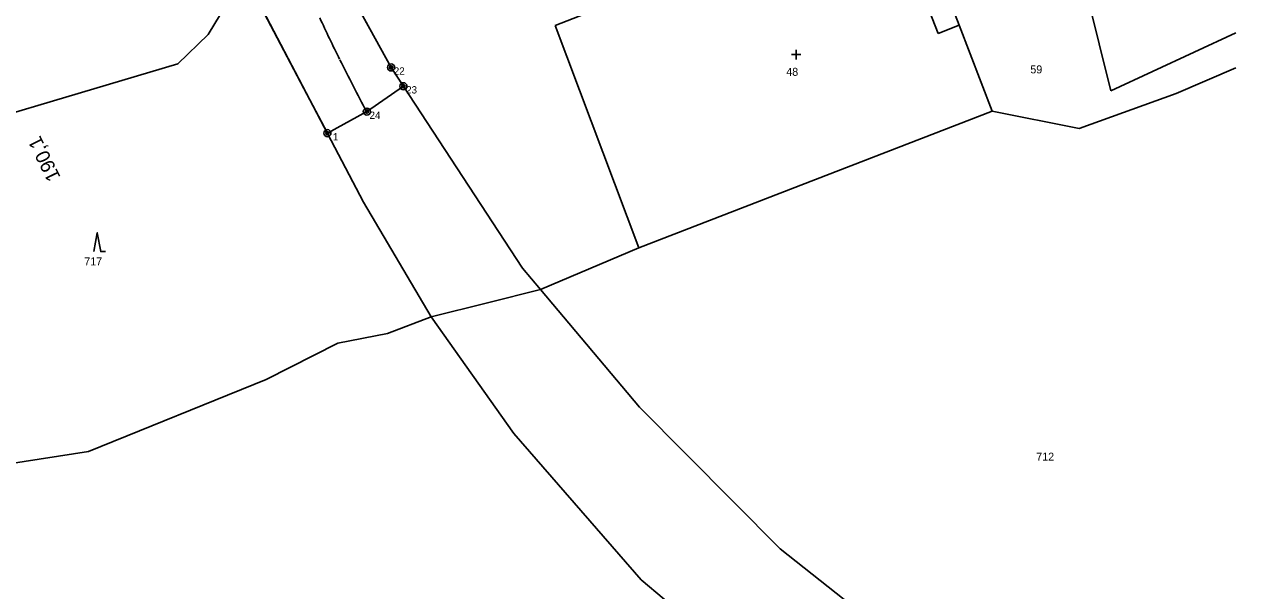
# Model space of a CAD drawing. Extents: x -812394 to -807601, y -1013097 to -1009266.
# Drawn here: x -809883 to -809625.5, y -1011159.4 to -1011039 of the extents above; entities that cross this region are included whole.
import ezdxf

# ---------------------------------------------------------------- set-up
doc = ezdxf.new("R2010")
doc.units = 0
for name, color, linetype in [('body', 7, 'Continuous'), ('cisla', 7, 'Continuous'), ('Default', 7, 'Continuous'), ('KN_HRANICE', 7, 'Continuous'), ('KN_KULTURY', 7, 'Continuous'), ('KN_PARCELY', 7, 'Continuous'), ('obvod_stavby', 7, 'Continuous'), ('SO02 - Železniční svršek', 7, 'Continuous'), ('Vrstva 7', 7, 'Continuous')]:
    doc.layers.add(name, color=color, linetype=linetype)

# ---------------------------------------------------------------- blocks, each defined once
blk = doc.blocks.new('308')
at = {"layer": 'Default'}
blk.add_lwpolyline([(-0.75, 0), (0, 4), (0.75, 0), (1.75, 0)], dxfattribs=at)
blk = doc.blocks.new('315')
at = {"layer": 'Default'}
for p, q in [((-1, 1), (1, 1)), ((0, 0), (0, 2))]:
    blk.add_line(p, q, dxfattribs=at)

msp = doc.modelspace()

# ---------------------------------------------------------------- linework, layer by layer
at = {"layer": 'body'}
for p, q in [((-809805.06, -1011048.21), (-809805.06, -1011048.21)), ((-809802.44, -1011052.2), (-809802.44, -1011052.2)), ((-809810.21, -1011057.6), (-809810.21, -1011057.6)), ((-809818.58, -1011062.18), (-809818.58, -1011062.18))]:
    msp.add_line(p, q, dxfattribs=at)
for centre, radius in [((-809805.06, -1011048.21), 0.75), ((-809805.06, -1011048.21), 0.35), ((-809802.44, -1011052.2), 0.75), ((-809802.44, -1011052.2), 0.35), ((-809810.21, -1011057.6), 0.75), ((-809810.21, -1011057.6), 0.35), ((-809818.58, -1011062.18), 0.75), ((-809818.58, -1011062.18), 0.35)]:
    msp.add_circle(centre, radius, dxfattribs=at)
at = {"layer": 'KN_HRANICE'}
for p, q in [((-809770.25, -1011039.27), (-809695.65, -1011010.24)), ((-809817.83, -1011024.91), (-809805.06, -1011048.21)), ((-809836.26, -1011028.53), (-809810.89, -1011076.81)), ((-809684.4, -1011039.22), (-809688.47, -1011028.73)), ((-809652.22, -1011053.19), (-809658.63, -1011027.44)), ((-809692.99, -1011030.49), (-809688.92, -1011040.98)), ((-809752.49, -1011086.54), (-809770.25, -1011039.27)), ((-809684.4, -1011039.22), (-809688.92, -1011040.98)), ((-809677.42, -1011057.54), (-809684.4, -1011039.22)), ((-809625.71, -1011040.87), (-809652.22, -1011053.19)), ((-809805.06, -1011048.21), (-809777.13, -1011090.84)), ((-809638.37, -1011053.74), (-809625.71, -1011048.27)), ((-809658.97, -1011061.19), (-809638.37, -1011053.74)), ((-809752.49, -1011086.54), (-809677.42, -1011057.54)), ((-809677.42, -1011057.54), (-809658.97, -1011061.19)), ((-809810.89, -1011076.81), (-809796.54, -1011101.19)), ((-809773.31, -1011095.41), (-809752.49, -1011086.54)), ((-809777.13, -1011090.84), (-809773.31, -1011095.41)), ((-809784.6, -1011098.22), (-809773.31, -1011095.41)), ((-809796.54, -1011101.19), (-809784.6, -1011098.22)), ((-809779.01, -1011125.97), (-809796.54, -1011101.19)), ((-809751.99, -1011157.11), (-809779.01, -1011125.97)), ((-809719.22, -1011184.3), (-809751.99, -1011157.11))]:
    msp.add_line(p, q, dxfattribs=at)
for points in [[(-809836.26, -1011028.53), (-809843.91, -1011041.24), (-809850.36, -1011047.46), (-809913.17, -1011066.15), (-809940.27, -1011066.63), (-809925.64, -1011129.13), (-809925.02, -1011131.63)], [(-809773.31, -1011095.41), (-809752.3, -1011120.38), (-809722.41, -1011150.52), (-809685.06, -1011180.11), (-809638.61, -1011207.44), (-809624.45, -1011211.08)], [(-809925.02, -1011131.63), (-809914.36, -1011132.31), (-809886.15, -1011132.43), (-809869.35, -1011129.81), (-809831.58, -1011114.54), (-809816.37, -1011106.77), (-809805.79, -1011104.77), (-809796.54, -1011101.19)]]:
    msp.add_lwpolyline(points, dxfattribs=at)
at = {"layer": 'obvod_stavby'}
for points in [[(-809819.54, -1010907.65), (-809819.54, -1010907.65), (-809817.34, -1010954.54), (-809819.55, -1010971.16), (-809814.76, -1010988.43), (-809814.4, -1010991.28), (-809823.56, -1010994.65), (-809817.83, -1011024.91), (-809805.06, -1011048.21), (-809802.44, -1011052.2)], [(-809865.72, -1010986.44), (-809864.77, -1010992.44), (-809859.52, -1010995.97), (-809854.51, -1011000.24), (-809850.32, -1011003.33), (-809836.26, -1011028.53), (-809823.58, -1011052.67), (-809818.58, -1011062.18)], [(-809802.44, -1011052.2), (-809810.25, -1011057.62)], [(-809818.58, -1011062.18), (-809810.21, -1011057.6)]]:
    msp.add_lwpolyline(points, dxfattribs=at)
at = {"layer": 'SO02 - Železniční svršek'}
for start, end in [(204.8126, 206.3264), (206.3405, 208.2649)]:
    msp.add_arc((-809483.92, -1010882.18), 370.5, start, end, dxfattribs=at)

# ---------------------------------------------------------------- block references
at = {"layer": 'KN_KULTURY'}
for name, p in [('315', (-809719.06, -1011046.5)), ('308', (-809867.46, -1011087.35))]:
    msp.add_blockref(name, p, dxfattribs=at)

# ---------------------------------------------------------------- texts
at = {"layer": 'cisla'}
for s, p in [(' 22', (-809805.06, -1011049.76)), (' 23', (-809802.44, -1011053.75)), (' 24', (-809810.21, -1011059.15)), ('  1', (-809818.58, -1011063.73))]:
    msp.add_text(s, height=1.552, dxfattribs=at).set_placement(p)
at = {"layer": 'KN_PARCELY'}
for s, p in [('59', (-809669.32, -1011049.48)), ('48', (-809721.15, -1011050)), ('717', (-809870.22, -1011090.28)), ('712', (-809668.06, -1011131.76))]:
    msp.add_text(s, height=1.7, dxfattribs=at).set_placement(p)
at = {"layer": 'Vrstva 7'}
msp.add_text('190,1', height=3, rotation=116.2264, dxfattribs=at).set_placement((-809875.18, -1011071.53))

doc.saveas('drawing.dxf')
